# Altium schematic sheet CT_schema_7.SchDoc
size 388 x 301 mm
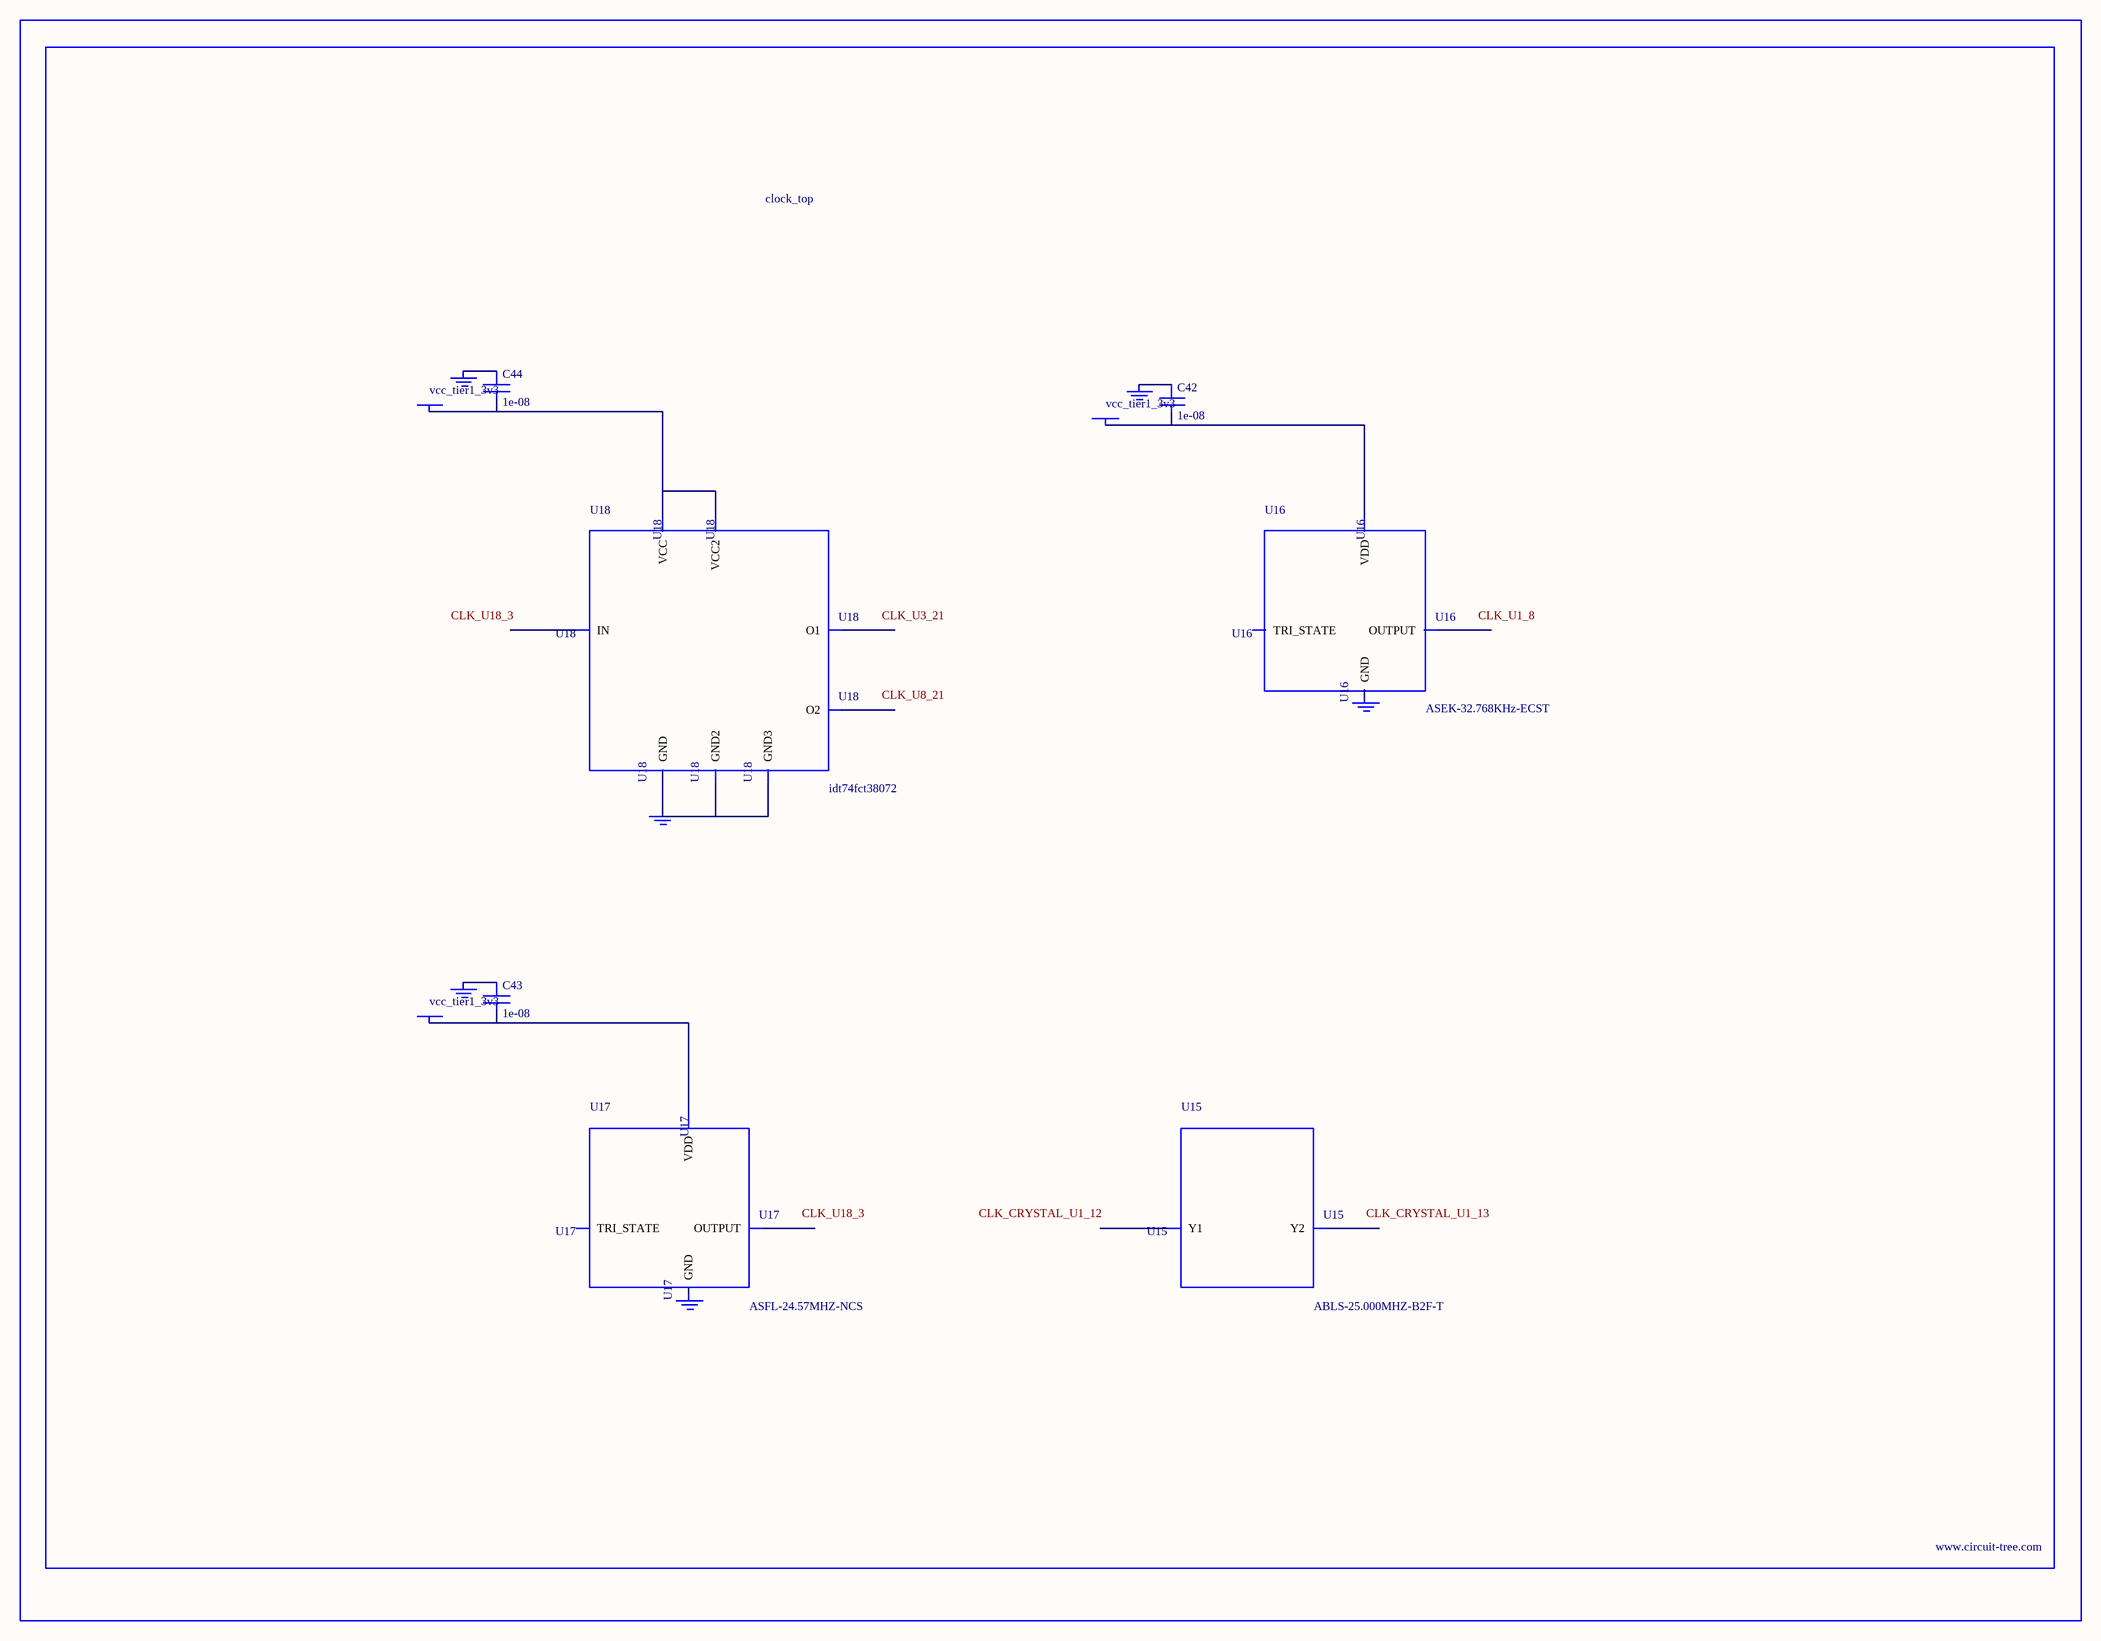
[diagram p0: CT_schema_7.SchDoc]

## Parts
BORDER6  (no value)
C42  1e-08  [C0402]
C43  1e-08  [C0402]
C44  1e-08  [C0402]
GND_INSTANCE_6_0  (no value)
GND_INSTANCE_6_1  (no value)
GND_INSTANCE_6_2  (no value)
GND_INSTANCE_6_3  (no value)
GND_INSTANCE_6_4  (no value)
GND_INSTANCE_6_5  (no value)
POWER_INSTANCE_6_0  vcc_tier1_3v3
POWER_INSTANCE_6_1  vcc_tier1_3v3
POWER_INSTANCE_6_2  vcc_tier1_3v3
U15  ABLS-25.000MHZ-B2F-T  [ABLS-25.000MHZ-B2F-T]
U16  ASEK-32.768KHz-ECST  [ASEK]
U17  ASFL-24.57MHZ-NCS  [ASFL1]
U18  idt74fct38072  [IDT74FCT38072]

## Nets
NetC42_1: C42.1 GND_INSTANCE_6_0.0(GND)
NetC42_2: C42.2 POWER_INSTANCE_6_0.0(PWR) U16.4(VDD)
NetC43_1: C43.1 GND_INSTANCE_6_2.0(GND)
NetC43_2: C43.2 POWER_INSTANCE_6_1.0(PWR) U17.4(VDD)
NetC44_1: C44.1 GND_INSTANCE_6_4.0(GND)
NetC44_2: C44.2 POWER_INSTANCE_6_2.0(PWR) U18.1(VCC) U18.2(VCC2)
NetGND_INSTANCE_6_5_0: GND_INSTANCE_6_5.0(GND) U18.4(GND) U18.5(GND2) U18.8(GND3)

Not connected (* = marked no-connect by the designer): GND_INSTANCE_6_1 0(GND); GND_INSTANCE_6_3 0(GND); U15 1(Y1) 2(Y2); U16 1(TRI_STATE) 2(GND) 3(OUTPUT); U17 1(TRI_STATE) 2(GND) 3(OUTPUT); U18 3(IN) 6(O2) 7(O1)

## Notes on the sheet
- Labels drawn without touching a wire or pin: CLK_CRYSTAL_U1_12, CLK_CRYSTAL_U1_13, CLK_U1_8, CLK_U3_21, CLK_U8_21, CLK_U18_3

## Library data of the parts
BORDER6 = BORDER_PAGE6
C42-C44 = C0402C103K3RAC
GND_INSTANCE_6_0-GND_INSTANCE_6_5 = GND
POWER_INSTANCE_6_0-POWER_INSTANCE_6_2 = PWR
